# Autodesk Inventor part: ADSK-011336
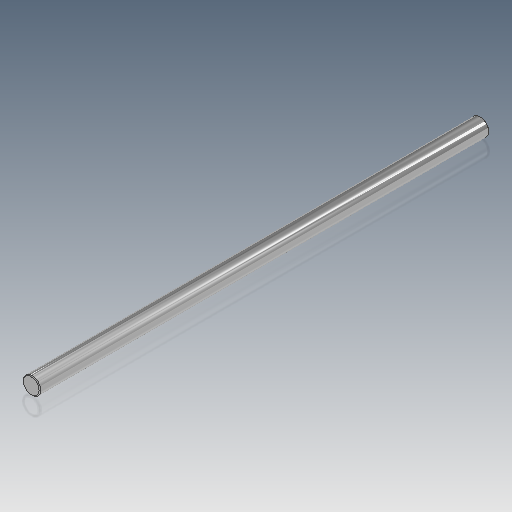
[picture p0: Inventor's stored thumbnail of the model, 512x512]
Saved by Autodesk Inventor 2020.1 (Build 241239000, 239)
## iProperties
Created: 1999-12
Part Number: ADSK-011336
Material: Acier doux
Description: SHFT-T,TH,FX,07-06,220,ADJUST,WIDTH,RH
Document SubType Name: Modeling
Designer: sspink
Density: 7.86 g/cm^3
Appearance: Chrom - poliert
Mass: 1273.68 g
Surface Area: 329.733 cm^2
Volume: 162.045 cm^3
Control State: 0
Checked Out: False
Master: False
Shininess: 0.0
Length Units: 11269
Angle Units: 11279
Time Units: 11290
Mass Units: 11283
Length Display Precision: 3
Angle Display Precision: 2
Compacted: True
Dimensions: 20x20x516 mm
Mass: 1,274 kg
DocNumber: ADSK-011336.ipt
Folder: 01 - Themengebiete\Simplification\01 - Packaging machine\
VDS_Category: 3D Komponenten
Density: 0.0
Volumn: 0.0
Area: 0.0
PropertySet Name: Model Information
Author: sspink
Revision Number: -
Title: shaft
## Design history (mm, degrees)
node "Solide1"
  node "Extrusion1" dims "d1" = 516, "d2" = 0
sketch "Sketch1"
  geometry: C1 r 10 at (0, 0); 1 further point
  constraints: 1 centre point, 1 coincident
  dimensions: "d0" = 20 diameter of C1
workaxis "Work Axis1"
workplane "Work Plane1"
workplane "Work Plane2"
chamfer "Fase1" distance "d16" = 1; stored, may be unused: second distance "d17" = 2, angle "d18" = 45 deg
node "Corps solides"
node "Corps surfaciques"
other parameters: "d3" = 0, "d12" = -139.7
